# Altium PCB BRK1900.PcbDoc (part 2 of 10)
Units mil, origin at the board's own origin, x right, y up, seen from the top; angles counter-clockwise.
Board outline 8858.27 x 5905.51 mil, 10 copper layers (L1-TOP, L2-GND, L3-SIG1, L4-GND, L5-PWR, L6-PWR, L7-GND, L8-SIG2, L9-GND, L10-BOT), stack 48.824 mil thick; 507 components, 607 nets, 2498 pads, 2210 vias.
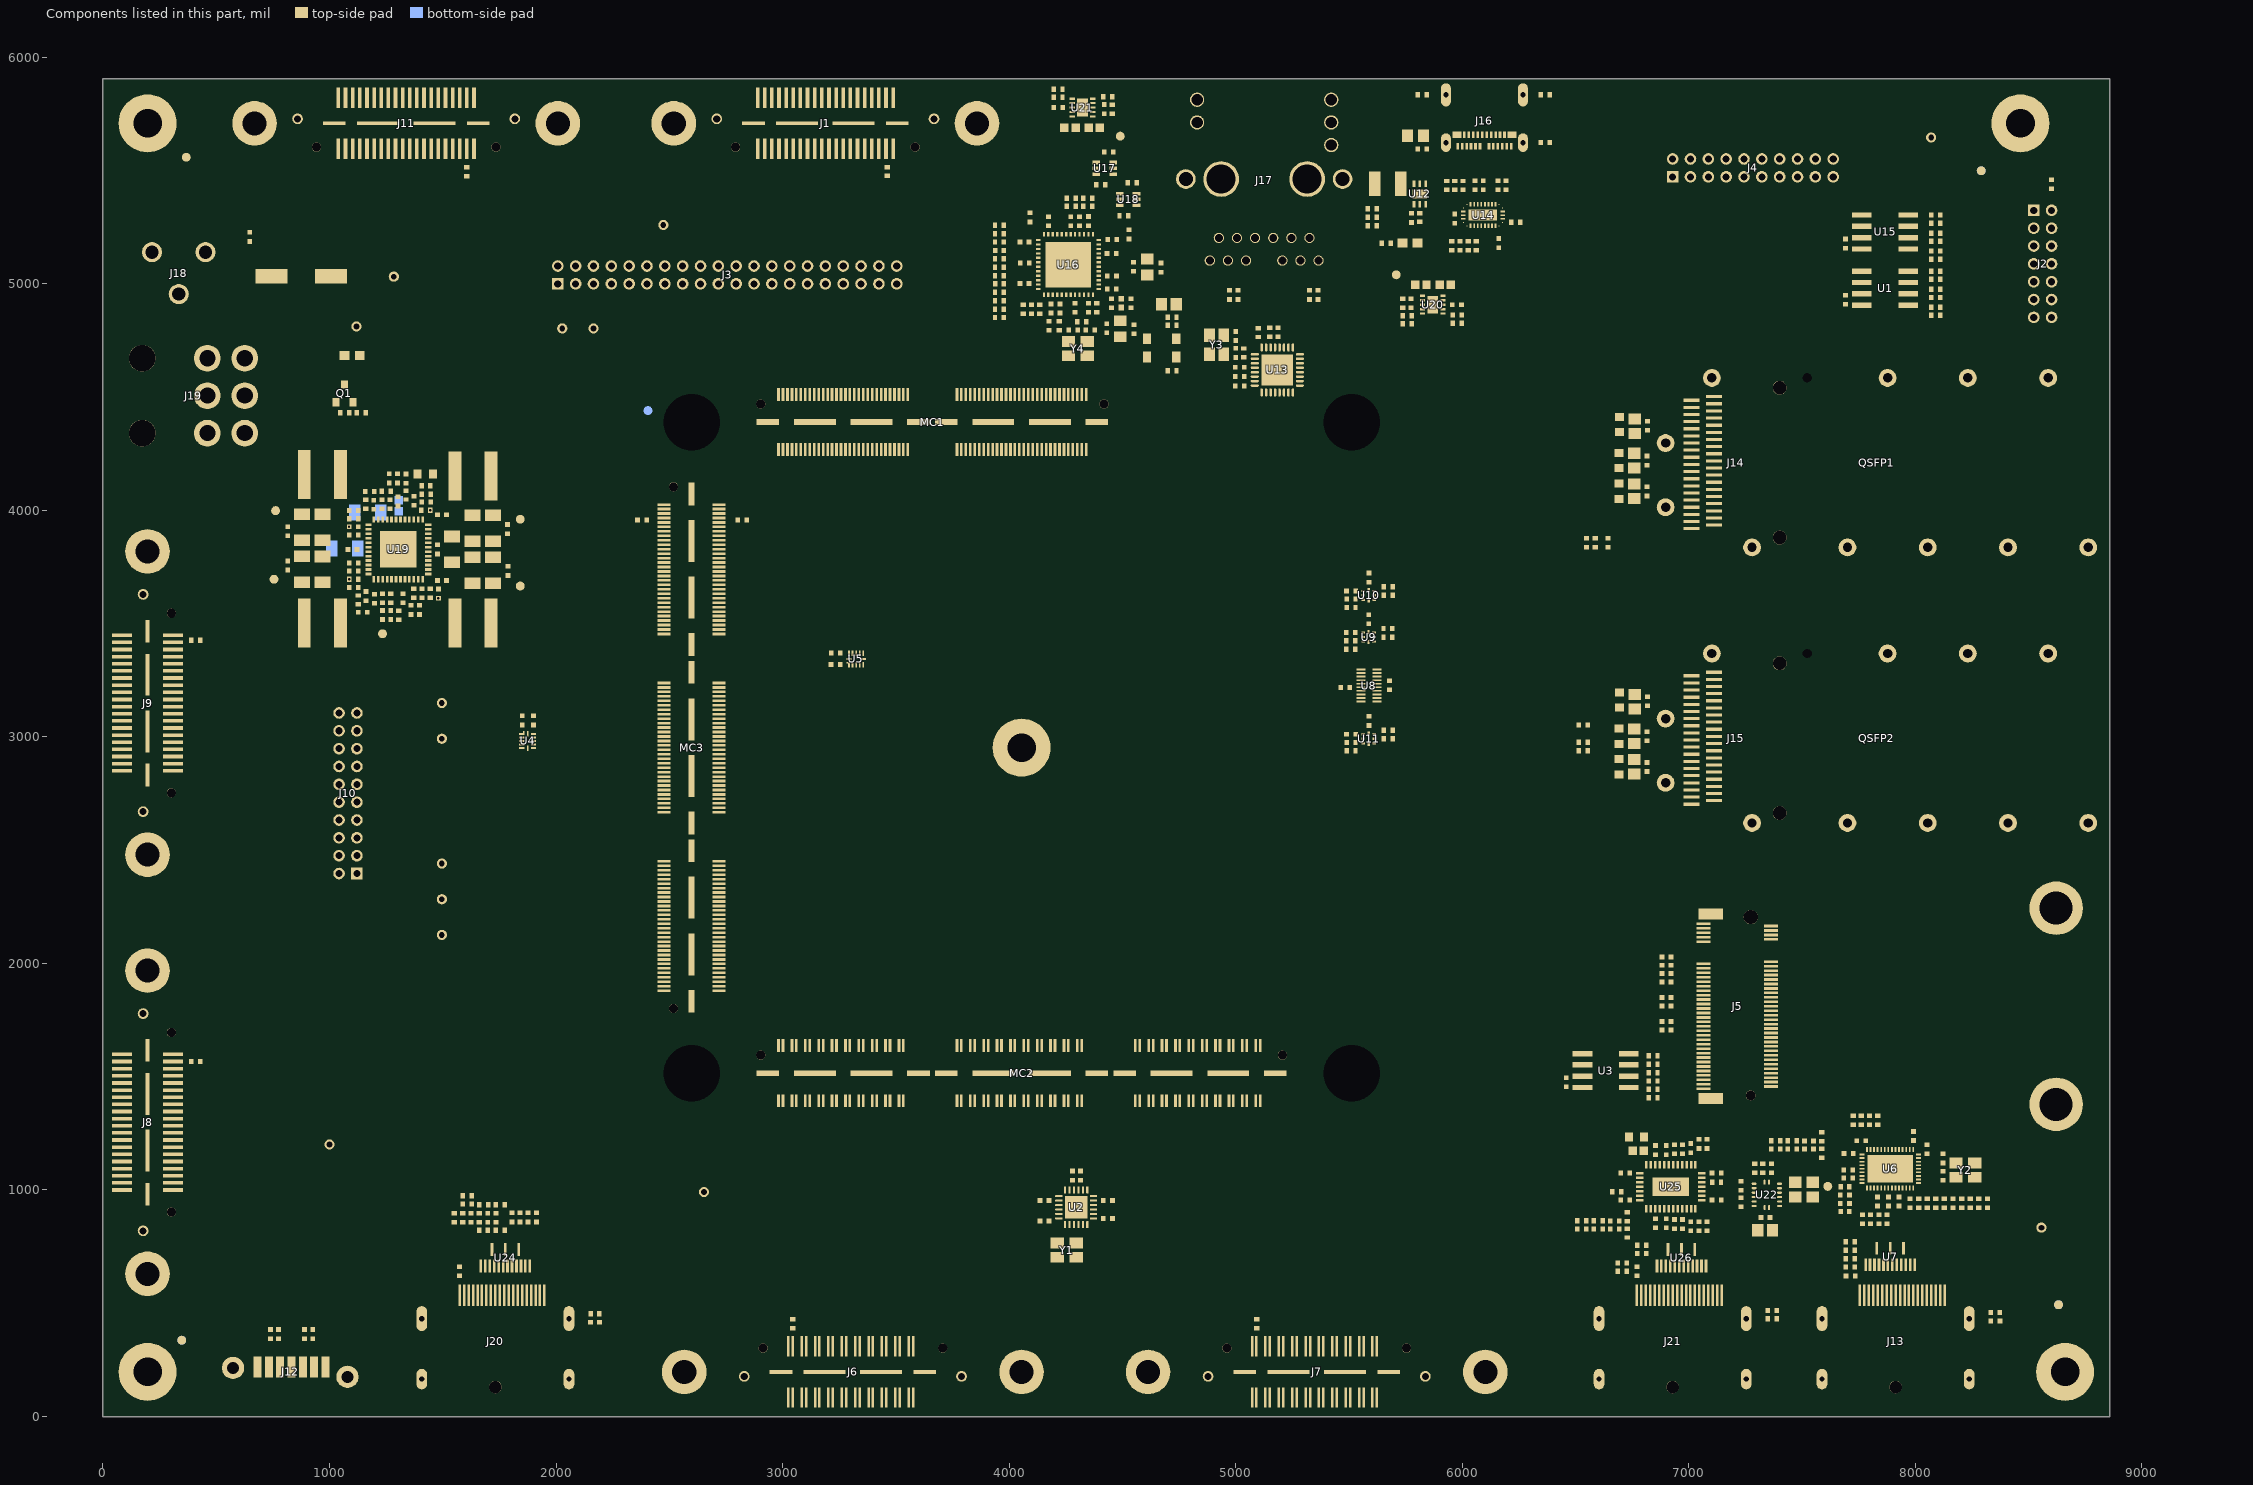
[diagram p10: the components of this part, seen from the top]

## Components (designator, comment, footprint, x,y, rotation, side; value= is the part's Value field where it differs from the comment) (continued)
R49 "CRCW04024K70JNED" RESC1005X06A#1 5673.46,3624.65 r0 top value="4.7 k"
R50 "SM-0402, 1%, 1/16W" RESC1005X06A#1 5508.46,3424.65 r180 top value="3.01 k"
R51 "SM-0402, 1%, 1/16W" RESC1005X06A#1 5508.46,3387.65 r180 top value="3.01 k"
R52 "CRCW06030000Z0EA" RESC1608N 6691.79,3003.24 r270 top value=0
R53 "CRCW06030000Z0EA" RESC1608N 6694,3163.18 r270 top value=0
R54 "CRCW06030000Z0EA" RESC1608N 6691.79,2868.24 r270 top value=0
R55 "SM-0402, 1%, 1/16W" RESC1005X06A#1 5509.46,3608.65 r180 top value="3.01 k"
R56 "SM-0402, 1%, 1/16W" RESC1005X06A#1 5509.46,3571.65 r180 top value="3.01 k"
R57 "CRCW04024K70JNED" RESC1005X06A#1 6535,3052.7 r180 top value="4.7 k"
R58 "CRCW04024K70JNED" RESC1005X06A#1 5672.46,3478.65 r0 top value="4.7 k"
R59 "CRCW04020000Z0ED" RESC1005X06A#1 6535,2976.7 r0 top value=0
R60 "CRCW04020000Z0ED" RESC1005X06A#1 6535,2938.7 r0 top value=0
R61 "SM-0402, 1%, 1/16W" RESC1005X06A#1 5509.46,2975.65 r180 top value="3.01 k"
R62 "SM-0402, 1%, 1/16W" RESC1005X06A#1 5509.46,2938.65 r180 top value="3.01 k"
R63 "CRCW04024K70JNED" RESC1005X06A#1 5673.46,3029.65 r0 top value="4.7 k"
R64 "CRCW04024K70JNED" RESC1005X06A#1 5673.46,2991.65 r0 top value="4.7 k"
R65 "CRCW04022K00FKED" RESC1005X06A#1 5665,5180 r180 top value="2.0 k"
R66 "CRCW040215K0FKED" RESC1005X06A#1 5813.06,5292.96 r90 top value="15 k"
R67 "CRCW04020000Z0ED" RESC1005X06A#2 5603,5331 r0 top value=0
R68 "CRCW040210K0FKED" RESC1005X06A#2 5603,5294 r0 top value="10.0 k"
R69 "CRCW04021K00FKED" RESC1005X06A#1 5150.41,4785.87 r270 top value="1 k"
R70 "CRCW04020000Z0ED" RESC1005X06A#2 5603,5257 r0 top value=0
R71 "CRCW0402499KFKEDC" RESC1005X06A#1 5990.41,5168.32 r270 top value="499 k"
R72 "CRCW0402887KFKED" RESC1005X06A#1 6062.41,5168.32 r270 top value="887 k"
R73 "CRCW04020000Z0ED" RESC1005X06A#1 5954.41,5168.32 r270 top value=0
R74 "CRCW040210K0FKED" RESC1005X06A#1 6026.41,5168.32 r270 top value="10.0 k"
R75 "CRCW04021M00JNED" RESC1005X06A#1 5036.41,4694.87 r270 top value="1 M"
R76 "CRCW04028K06FKED" RESC1005X06A#1 5100,4785 r270 top value="8.06 k"
R77 "CRCW04020000Z0ED" RESC1005X06A#1 6367,5834 r0 top value=0
R78 "CRCW04020000Z0ED" RESC1005X06A#1 5824,5834 r180 top value=0
R79 "CRCW04020000Z0ED" RESC1005X06A#1 6367,5624 r0 top value=0
R80 "CRCW040210K0FKED" RESC1005X06A#1 5931.41,5434.32 r90 top value="10.0 k"
R81 "CRCW040210K0FKED" RESC1005X06A#1 5967.41,5434.32 r90 top value="10.0 k"
R82 "CRCW0402210KFKED" RESC1005X06A#1 6236.09,5272.32 r0 top value="210 k"
R83 "CRCW040210K0FKED" RESC1005X06A#1 6003.41,5434.32 r270 top value="10.0 k"
R84 "CRCW040210K0FKED" RESC1005X06A#1 8091,5145 r0 top value="10.0 k"
R85 "CRCW040210K0FKED" RESC1005X06A#1 8091,5224 r0 top value="10.0 k"
R86 "CRCW040210K0FKED" RESC1005X06A#1 8091,5304 r0 top value="10.0 k"
R87 "CRCW040210K0FKED" RESC1005X06A#1 8091,5109 r180 top value="10.0 k"
R88 "CRCW040210K0FKED" RESC1005X06A#1 8091,5188 r180 top value="10.0 k"
R89 "CRCW040210K0FKED" RESC1005X06A#1 8091,5268 r180 top value="10.0 k"
R90 "CRCW04024K75FKED" RESC1005X06A#2 3957.49,4962.42 r180 top value="4.75 k"
R91 "CRCW04024K75FKED" RESC1005X06A#2 3957.49,4888.42 r180 top value="4.75 k"
R92 "CRCW04024K75FKED" RESC1005X06A#2 3957.49,5258.42 r180 top value="4.75 k"
R93 "CRCW04024K75FKED" RESC1005X06A#2 3957.49,5184.42 r180 top value="4.75 k"
R94 "CRCW04024K75FKED" RESC1005X06A#2 3957.49,5110.42 r180 top value="4.75 k"
R95 "CRCW04024K75FKED" RESC1005X06A#2 3957.49,5036.42 r180 top value="4.75 k"
R96 "CRCW0402240RFKED" RESC1005X06A#2 4405,5438 r180 top value=240
R97 "CRCW0402240RFKED" RESC1005X06A#2 4507,5300 r180 top value=240
R98 "CRCW04024K75FKED" RESC1005X06A#2 3957.49,4925.42 r0 top value="4.75 k"
R99 "CRCW04024K75FKED" RESC1005X06A#2 3957.49,4851.42 r0 top value="4.75 k"
R100 "CRCW04024K75FKED" RESC1005X06A#2 3957.49,5221.42 r0 top value="4.75 k"
R101 "CRCW04024K75FKED" RESC1005X06A#2 3957.57,5147.41 r0 top value="4.75 k"
R102 "CRCW04024K75FKED" RESC1005X06A#2 3957.39,5073.41 r0 top value="4.75 k"
R103 "CRCW04024K75FKED" RESC1005X06A#2 3957.63,4999.68 r0 top value="4.75 k"
R104 "CRCW040210K0FKED" RESC1005X06A#1 4440,5582 r180 top value="10.0 k"
R105 "CRCW04022K49FKED" RESC1005X06A#1 4062,4888 r270 top value="2.49 k"
R106 "CRCW04022K49FKED" RESC1005X06A#1 4099,4888 r270 top value="2.49 k"
R107 "CRCW04022K49FKED" RESC1005X06A#1 4136,4888 r270 top value="2.49 k"
R108 "CRCW04024K75FKED" RESC1005X06A#2 4176,4815 r270 top value="4.75 k"
R109 "CRCW040212K1FKED" RESC1005X06A#2 4387.06,4894.45 r270 top value="12.1 k"
R110 "CRCW040210K0FKED" RESC1005X06A#2 4275.06,5342.14 r180 top value="10.0 k"
R111 "CRCW040210K0FKED" RESC1005X06A#2 4346.74,5342.14 r0 top value="10.0 k"
R112 "CRCW040210K0FKED" RESC1005X06A#1 4543,5447 r180 top value="10.0 k"
R113 "CRCW04021M00JNED" RESC1005X06A#2 4321.06,4833.14 r180 top value="1 M"
R114 "CRCW04024K75FKED" RESC1005X06A#2 4222.06,4815.14 r90 top value="4.75 k"
R115 "CRCW04021K00FKED" RESC1005X06A#2 4275.06,5378.14 r0 top value="1 k"
R116 "CRCW04021K00FKED" RESC1005X06A#2 4346.74,5378.14 r180 top value="1 k"
R117 "CRCW04020000Z0ED" RESC1005X06A#2 4719.28,4616.57 r0 top value=0
R118 "CRCW04022K49FKED" RESC1005X06A#2 4719.28,4816.57 r180 top value="2.49 k"
R119 "CRCW040210K0FKED" RESC1005X06A#2 4719.28,4852.57 r0 top value="10.0 k"
R120 "CRCW040210K0FKED" RESC1005X06A#1 1270.29,3611.53 r270 top value="10.0 k"
R121 "CRCW040210K0FKED" RESC1005X06A#1 1250.29,4084.53 r0 top value="10.0 k"
R122 "SM-0402, 1%, 1/16W" RESC1005X06A#1 1444.58,3633.64 r270 top value="31.6 k"
R123 "SM-0402, 1%, 1/16W" RESC1005X06A#1 1408.58,3633.64 r90 top value="10.0 k"
R124 "CRCW040215K0FKED" RESC1005X06A#1 1372.58,3633.64 r270 top value="15 k"
R125 "SM-0402, 1%, 1/16W" RESC1005X06A#1 1425.27,4000.64 r0 top value="31.6 k"
R126 "SM-0402, 1%, 1/16W" RESC1005X06A#1 1426.58,4071.64 r180 top value="10.0 k"
R127 "CRCW040215K0FKED" RESC1005X06A#1 1337.58,4067.72 r90 top value="15 k"
R128 "CRCW040252K3FKED" RESC1005X06A#1 1106.58,3963.64 r180 top value="52.3 k"
R129 "CRCW040215K0FKED" RESC1005X06A#1 1159.58,4026.64 r90 top value="15 k"
R130 "SM-0402, 1%, 1/16W" RESC1005X06A#1 1106.58,3999.64 r0 top value="10.0 k"
R131 "CRCW040210K0FKED" RESC1005X06A#1 1234.29,3611.53 r270 top value="10.0 k"
R132 "CRCW040252K3FKED" RESC1005X06A#1 1106.58,3695.64 r180 top value="52.3 k"
R133 "CRCW040215K0FKED" RESC1005X06A#1 1126.29,3604.53 r270 top value="15 k"
R134 "CRCW0402374KFKED" RESC1005X06A#1 1305.4,3537.55 r90 top value="374 k"
R135 "SM-0402, 1%, 1/16W" RESC1005X06A#1 1106.9,3659.64 r0 top value="10.0 k"
R136 "CRCW06030000Z0EA" RESC1608N 1423,4160 r180 top value=0
R137 "CRCW040210K0JNED" RESC1005X06A#1 1426,4108 r0 top value="10 k"
R138 "CRCW04022K00FKED" RESC1005X06A#1 1140,4431 r180 top value="2.0 k"
R139 "CRCW040210K0FKED" RESC1005X06A#1 5737.94,4914.77 r90 top value="10.0 k"
R140 "CRCW040210K0FKED" RESC1005X06A#1 4456,5771.46 r270 top value="10.0 k"
R141 "CRCW0402237KFKED" RESC1005X06A#1 7327,1096.48 r90 top value="237 k"
R142 "CRCW04028K06FKED" RESC1005X06A#1 5757.94,4859.77 r180 top value="8.06 k"
R143 "CRCW040220K0FKED" RESC1005X06A#1 4436,5826.46 r0 top value="20.0 k"
R144 "CRCW040210R0FKED" RESC1005X06A#1 7231,945.48 r270 top value=10
R145 "CRCW04020000Z0ED" RESC1005X06A#1 5977.94,4862.77 r180 top value=0
R146 "CRCW04020000Z0ED" RESC1005X06A#1 4216,5823.46 r0 top value=0
R147 "CRCW0402237KFKED" RESC1005X06A#1 7291,1096.48 r270 top value="237 k"
R148 "CRCW040210K0FKED" RESC1005X06A#1 1068,4431 r0 top value="10.0 k"
R149 "CRCW040210K0JNED" RESC1005X06A#1 5758.25,4823.77 r180 top value="10 k"
R150 "CRCW04020000Z0ED" RESC1005X06A#1 5977.94,4826.77 r0 top value=0
R151 "CRCW04020000Z0ED" RESC1005X06A#1 4216,5859.46 r180 top value=0
R153 "CRCW040249R9FKEDC" RESC1005X06A#1 1753.53,935 r180 top value=49.9
R154 "CRCW0402100KFKED" RESC1005X06A#1 1754.21,822 r180 top value="100 k"
R155 "CRCW04021M00FKEDC" RESC1005X06A#1 2172,453 r180 top value="1 M"
R156 "CRCW04021M00FKEDC" RESC1005X06A#1 1550.53,878 r270 top value="1 M"
R157 "CRCW04021M00FKEDC" RESC1005X06A#1 1587.53,878 r270 top value="1 M"
R158 "CRCW040249R9FKEDC" RESC1005X06A#1 1680.53,935 r180 top value=49.9
R159 "CRCW0402100KFKED" RESC1005X06A#2 1624.53,878 r90 top value="100 k"
R160 "CRCW06030000Z0EA" RESC1608N 6769.36,1233.44 r0 top value=0
R161 "CRCW04021K20FKEDC" RESC1005X06A#1 6681.88,991.59 r0 top value="1.2 k"
R162 "CRCW04021M00FKEDC" RESC1005X06A#1 7369,431 r180 top value="1 M"
R163 "CRCW04021M00FKEDC" RESC1005X06A#1 6706.53,642 r0 top value="1 M"
R164 "CRCW04021M00FKEDC" RESC1005X06A#1 6706.53,678 r0 top value="1 M"
R165 "CRCW04020000Z0ED" RESC1005X06A#1 7122.83,1034.44 r180 top value=0
R166 "CRCW0402100KFKED" RESC1005X06A#1 6793.53,756 r180 top value="100 k"
R167 "CRCW0402100KFKED" RESC1005X06A#1 1679.84,822 r180 top value="100 k"
R168 "CRCW04022K49FKED" RESC1005X06A#1 1608.53,938 r180 top value="2.49 k"
R169 "CRCW04021K50FKED" RESC1005X06A#1 1608.53,975 r0 top value="1.5 k"
R170 "CRCW040249R9FKEDC" RESC1005X06A#1 6600,864 r0 top value=49.9
R171 "CRCW0402100KFKED" RESC1005X06A#1 6729,881.68 r270 top value="100 k"
R172 "CRCW040249R9FKEDC" RESC1005X06A#1 6600,828 r180 top value=49.9
R173 "CRCW0402100KFKED" RESC1005X06A#1 6729,810 r270 top value="100 k"
R174 "CRCW04022K49FKED" RESC1005X06A#1 6528,828 r180 top value="2.49 k"
R175 "CRCW04021K50FKED" RESC1005X06A#1 6528,864 r0 top value="1.5 k"
R176 "CRCW04022K49FKED" RESC1005X06A#1 7385,1217 r180 top value="2.49 k"
R177 "CRCW04021K50FKED" RESC1005X06A#1 7385,1181 r0 top value="1.5 k"
R178 "CRCW040249R9FKEDC" RESC1005X06A#1 7457,1217 r0 top value=49.9
R179 "CRCW040249R9FKEDC" RESC1005X06A#1 7457,1181 r180 top value=49.9
R180 "CRCW040210R0FKED" RESC1005X06A#1 7713.53,734 r0 top value=10
R181 "CRCW040210R0FKED" RESC1005X06A#1 1661.53,878 r270 top value=10
R182 "CRCW040210R0FKED" RESC1005X06A#1 6793.53,720 r0 top value=10
SO1 "Standoff" 9774025151R 8622.05,2244.09 r0 top locked
SO2 "Standoff" 9774025151R 8622.05,1377.95 r0 top locked
TP1 "+1.8V" TP-PTH-25/45 2653,991 r90 top
TP2 "DGND" TP-PTH-25/45 8557,834 r0 top
TP3 "+3.3V" TP-PTH-25/45 2165.35,4803.15 r90 top
TP4 "VREF_67" TP-PTH-25/45 1496.06,2992.13 r90 top
TP5 "DGND" TP-PTH-25/45 1000,1201 r90 top
TP6 "VCCO_28" TP-PTH-25/45 2474,5260 r90 top
TP7 "VCCO_68" TP-PTH-25/45 1496.06,2440.94 r90 top
TP8 "DGND" TP-PTH-25/45 1284,5032 r180 top
TP9 "VREF_28" TP-PTH-25/45 2027.56,4803.15 r90 top
TP10 "VREF_68" TP-PTH-25/45 1496.06,2283.46 r90 top
TP11 "DGND" TP-PTH-25/45 8070,5646 r90 top
TP12 "VCCO_67" TP-PTH-25/45 1119,4812 r90 top
TP13 "VCCO_87_88" TP-PTH-25/45 1496.06,2125.98 r90 top
TP14 "VCC_PSBATT" TP-PTH-25/45 1496.06,3149.61 r90 top
TP15 "+3.3V_QSFP" TP-SMD40 1842,3666 r90 top
TP16 "+3.3V_AUX" TP-SMD40 1842,3961 r90 top
TP17 "+5V_AUX" TP-SMD40 762,3999 r90 top
TP18 "+5V_SZG" TP-SMD40 755,3696 r90 top
TP19 "TESTPOINT-SMD40" TP-SMD40 1234.29,3455.53 r0 top
TP20 "+1.2V_DP" TP-SMD40 7614,1016 r90 top
TP21 "+1.8V_AUX" TP-SMD40 5709,5040 r90 top
TP22 "+1.2V_ETH" TP-SMD40 4491,5652 r90 top
U1 "24FC256-I/SN" SO-G8 7867,4981 r90 top
U2 "SI5338B-B-GM" Si5338 4296.23,923.79 r90 top
U3 "24FC256-I/SN" SO-G8 6633.6,1527.15 r90 top
U4 "TXB0304RUTR" PUQFN-N12 1875,2982 r0 top
U5 "TXB0304RUTR" PUQFN-N12 3325,3344 r90 top
U6 "MCDP6000C1" MCDP6000 7889.13,1093.63 r90 top
U7 "TPD8S009DSMR" TPD8S009DSMR 7889.17,706.42 r0 top locked
U8 "TXB0108DQSR" TXB0108DQSR 5588,3227 r270 top
U9 "FXMAR2102L8X" FXMAR2102L8X 5587,3441 r0 top
U10 "FXMAR2102L8X" FXMAR2102L8X 5588,3625 r0 top
U11 "FXMAR2102L8X" FXMAR2102L8X 5588,2992 r0 top
U12 "TPS2553DRV" S-PWSON-N6 5813,5397 r0 top
U13 "USB3320C-EZK" QFN-32 5183.95,4620.06 r90 top
U14 "HD3SS3220RNH" WQFN-30 6092.38,5303.24 r90 top
U15 "24AA025E48-I/SN" SO-G8 7867,5229 r90 top
U16 "KSZ9031RNXCA" QFN-48 4261.9,5085.28 r180 top
U17 "FDG6301" SOT363-6N 4422.23,5510 r0 top
U18 "FDG6301" SOT363-6N 4525,5373 r0 top
U19 "TPS65400RGZ" PVQFN-48 1303.58,3827.64 r180 top locked
U20 "TPS7A9001DSK" TPS7A90 5870,4908 r0 top
U21 "TPS7A9001DSK" TPS7A90 4323.94,5778.23 r180 top
U22 "EP53F8QI" EP53F8QI 7345,978.48 r180 top
U24 "TPD8S009DSMR" TPD8S009DSMR 1776.25,701.42 r0 top locked
U25 "SN65DP141RLJ" SN65DP141 6921.61,1014.88 r270 top
U26 "TPD8S009DSMR" TPD8S009DSMR 6967.98,701.27 r0 top locked
Y1 "FA-238 25.0000MB-C3" OSC_SMD_32x25 4254.23,734.79 r180 top
Y2 "ABM8-25.000MHZ-D2Y-T" OSC_SMD_32x25 8221.77,1087.26 r180 top
Y3 "T12BC1-19.200MHZ-T" OSC_SMD_32x25 4915.91,4730.6 r90 top
Y4 "ABM8-25.000MHZ-D2Y-T" OSC_SMD_32x25 4303.79,4713.64 r0 top

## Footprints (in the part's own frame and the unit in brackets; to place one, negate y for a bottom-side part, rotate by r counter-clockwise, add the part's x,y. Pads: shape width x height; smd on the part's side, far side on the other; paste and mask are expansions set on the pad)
0455580003 [mm]
  round 3 hole 3 unplated: 0(-4.2,7.3) 0(4.2,7.3)
  round 3 hole 1.8: 1(-4.2,0) 2(0,0) 3(4.2,0) 4(-4.2,-4.2) 5(0,-4.2) 6(4.2,-4.2)
  silkscreen extent -7,1 7,14
0472720001 [mm]
  rect 0.28x2.4 smd: 1(5.5,10.28) 2(5,10.28) 3(4.5,10.28) 4(4,10.28) 5(3.5,10.28) 6(3,10.28) 7(2.5,10.28) 8(2,10.28) 9(1.5,10.28) 10(1,10.28) 11(0.5,10.28) 12(0,10.28) 13(-0.5,10.28) 14(-1,10.28) 15(-1.5,10.28) 16(-2,10.28) 17(-2.5,10.28) 18(-3,10.28) 19(-3.5,10.28) 20(-4,10.28)
  round 1.4 hole 1.4 unplated paste-20 mask+0.076: M1(0,0)
  oval 1.2x2.8 hole 0.6 slot 2.2 at 90 deg paste-20 mask+0.076: SHELL1(-8.25,7.68) SHELL2(8.25,7.68)
  oval 1.2x2.3 hole 0.6 slot 1.7 at 90 deg paste-20 mask+0.076: SHELL3(8.25,0.9) SHELL4(-8.25,0.9)
  silkscreen extent -8.51,-4.4 8.5,10.2
1054500101 [mm]
  rect 0.3x0.7 smd: A1(1.32,0.41) A2(1.82,0.41) A3(2.32,0.41) A4(2.82,0.41) A5(3.32,0.41) A6(3.82,0.41) A7(4.82,0.41) A8(5.32,0.41) A9(5.82,0.41) A10(6.32,0.41) A11(6.82,0.41) A12(7.32,0.41) B2(6.57,-0.89) B3(6.07,-0.89) B4(5.57,-0.89) B5(5.07,-0.89) B6(4.57,-0.89) B7(4.07,-0.89) B8(3.57,-0.89) B9(3.07,-0.89) B10(2.57,-0.89) B11(2.07,-0.89)
  rect 1x0.7 smd: B1(7.42,-0.89) B12(1.22,-0.89)
  oval 1.1x2.1 hole 0.6 slot 1.6 at 90 deg: M1(0,0) M2(8.64,0)
  oval 1.1x2.6 hole 0.6 slot 2.1 at 90 deg: M3(8.64,-5.36) M4(0,-5.36)
  silkscreen extent -0.18,-7.3 8.82,-1.4
9774025151R [mm]
  round 6 hole 3.7: 1(0,0)
CAPAE9083X70N [mm] "Aluminum Electrolytic Capacitor, Body 8.30x8.30x7.00mm, IPC Medium Density"
  rect 3.6x1.65 smd: 1(-3.325,0) 2(3.325,0)
  silkscreen extent -4.25,-4.25 4.25,4.25
CAPC1005X06A#1 [mm] "Chip Capacitor, 2-Leads, Body 1.00x0.50mm, OK custom footprint"
  rect 0.52x0.55 smd mask+0.051: 1(-0.51,0) 2(0.51,0)
CAPC1005X06A#2 [mm] "Chip Capacitor, 2-Leads, Body 1.00x0.50mm, OK custom footprint"
  rect 0.52x0.55 smd: 1(-0.51,0) 2(0.51,0)
CAPC1608X09N [mm] "Chip Capacitor, 2-Leads, Body 1.60x0.80mm, IPC Medium Density"
  rect 0.95x0.95 smd: 1(-0.625,0) 2(0.625,0)
  silkscreen extent -0.8,-0.68 0.8,0.68, body extent -0.85,-0.45 0.85,0.45, height 0.9
CAPC2012X14N [mm] "Chip Capacitor, 2-Leads, Body 2.00x1.25mm, IPC Medium Density"
  rect 1.25x1.4 smd: 1(-0.825,0) 2(0.825,0)
  silkscreen extent -0.6,-0.88 0.6,0.88, body extent -1.05,-0.67 1.05,0.67, height 1.4
CAPC3216N [mm] "Chip Capacitor, Body 3.2x1.6mm, IPC Medium Density"
  rect 1.3x1.8 smd: 1(-1.45,0) 2(1.45,0)
  silkscreen extent -1.2,-1.08 1.2,1.08, body extent -1.7,-0.9 1.7,0.9, height 1.35
CAPC3225N [mm] "Chip Capacitor, Body 3.2x2.5mm, IPC Medium Density"
  rect 1.3x2.7 smd: 1(-1.45,0) 2(1.45,0)
  silkscreen extent -1.2,-1.53 1.2,1.53, body extent -1.7,-1.35 1.7,1.35, height 1.35
CD1608-0603-PIN1-CATHODE [mm] "Chip Diode; Body 1.6 x 0.8 mm (LxW typ)"
  rect 1.1x1 smd: 1(-0.85,0) 2(0.85,0)
  silkscreen extent -1.58,-0.68 0.6,0.68
CUI-PJ102A [mm] "2.1mm/5.5mm DC power jack"
  round 2.25 hole 1.5: 1(0,13.7) 2(0,7.7) 3(4.7,10.7)
  silkscreen extent -4.5,0 4.5,14.5
EP53F8QI [mm] "1.5A Voltage Mode Synchronous Buck PWM  DC-DC Converter"
  oval 0.55x0.25 smd mask+0.076: 1(-1.425,1.25) 2(-1.425,0.75) 3(-1.425,0.25) 4(-1.425,-0.25) 5(-1.425,-0.75) 6(-1.425,-1.25) 9(1.425,-1.25) 10(1.425,-0.75) 11(1.425,-0.25) 12(1.425,0.25) 13(1.425,0.75) 14(1.425,1.25)
  oval 0.25x0.55 smd mask+0.076: 7(-0.25,-1.425) 8(0.25,-1.425) 15(0.25,1.425) 16(-0.25,1.425)
  silkscreen extent -1.93,-1.56 1.5,1.93
FID1MM/2MM-SS [mm] "Fiducial 1mm copper, 2mm soldermask, single-side"
  round 1 smd paste-0.5 mask+0.5: FID?(0,0)
FXMAR2102L8X [mm]
  rect 0.4x0.25 smd mask+0.051: 1(-0.605,0.5) 2(-0.605,0) 3(-0.605,-0.5) 5(0.605,-0.5) 6(0.605,0) 7(0.605,0.5)
  rect 0.25x0.45 smd mask+0.051: 4(0,-0.575) 8(0,0.575)
HDR2X7-2MM [mm] "2mm 2x7 header"
  rect 1.3x1.3 hole 0.8: 1(-6,-1)
  round 1.3 hole 0.8: 2(-6,1) 3(-4,-1) 4(-4,1) 5(-2,-1) 6(-2,1) 7(0,-1) 8(0,1) 9(2,-1) 10(2,1) 11(4,-1) 12(4,1) 13(6,-1) 14(6,1)
  silkscreen extent -7,-2 7,2
HDR2X10-2MM [mm] "2mm 2x10 header"
  rect 1.3x1.3 hole 0.8: 1(-9,-1)
  round 1.3 hole 0.8: 2(-9,1) 3(-7,-1) 4(-7,1) 5(-5,-1) 6(-5,1) 7(-3,-1) 8(-3,1) 9(-1,-1) 10(-1,1) 11(1,-1) 12(1,1) 13(3,-1) 14(3,1) 15(5,-1) 16(5,1) 17(7,-1) 18(7,1) 19(9,-1) 20(9,1)
  silkscreen extent -10,-2 10,2
HDR2X20-2MM [mm] "2mm 2x20 header"
  rect 1.3x1.3 hole 0.8: 1(-19,-1)
  round 1.3 hole 0.8: 2(-19,1) 3(-17,-1) 4(-17,1) 5(-15,-1) 6(-15,1) 7(-13,-1) 8(-13,1) 9(-11,-1) 10(-11,1) 11(-9,-1) 12(-9,1) 13(-7,-1) 14(-7,1) 15(-5,-1) 16(-5,1) 17(-3,-1) 18(-3,1) 19(-1,-1) 20(-1,1) 21(1,-1) 22(1,1) 23(3,-1) 24(3,1) 25(5,-1) 26(5,1) 27(7,-1) 28(7,1) 29(9,-1) 30(9,1) 31(11,-1) 32(11,1) 33(13,-1) 34(13,1) 35(15,-1) 36(15,1) 37(17,-1) 38(17,1) 39(19,-1) 40(19,1)
  silkscreen extent -20,-2 20,2
INDC1005X05N [mm] "Chip Inductor, 2-Leads, Body 1.01x0.50mm, IPC Medium Density"
  rect 0.66x0.64 smd: 1(-0.5,0) 2(0.5,0)
  body extent -0.61,-0.3 0.61,0.3, height 0.5
JSO-0515-01 [mil]
  round 0 hole 250 unplated: 1(0,0)
  Keep-Out Layer region: 0,-157.48 -60.27,-145.49 -111.36,-111.36 -145.49,-60.27 -157.48,0 -157.48,0 -145.49,60.27 -111.36,111.36 -60.27,145.49 0,157.48 0,157.48 60.27,145.49 111.36,111.36 145.49,60.27 157.48,0 157.48,0 145.49,-60.27 111.36,-111.36 60.27,-145.49 0,-157.48
L829-1J1T-43 [mm] "Ethernet MagJack"
  round 1.15 hole 0.89: 1(5.08,6.604) 2(3.048,6.604) 3(1.016,6.604) 4(-1.016,6.604) 5(-3.048,6.604) 6(-5.08,6.604) 7(6.096,9.144) 8(4.064,9.144) 9(2.032,9.144) 10(-2.032,9.144) 11(-4.064,9.144) 12(-6.096,9.144)
  round 1.6 hole 1.27: 13(7.52,-6.35) 14(7.52,-8.89) 15(-7.52,-3.81) 16(-7.52,-6.35) 17(-7.52,-8.89)
  round 2.2 hole 1.575: S1(-8.79,0) S2(8.79,0)
  round 4 hole 3.251: T1(-4.825,0) T2(4.825,0)
  silkscreen extent -8.9,-13.3 8.9,10.9
M2-CONNECTOR_M-KEYING [mm] "M-2 Connector, 67-pin, M Keying"
  rect 1.2x2.75 smd mask+0.051: 1(-10.35,4.5) 1(10.35,4.5)
  rect 0.3x1.55 smd mask+0.051: 1(-9.25,5.275) 2(-9,-2.275) 3(-8.75,5.275) 4(-8.5,-2.275) 5(-8.25,5.275) 6(-8,-2.275) 7(-7.75,5.275) 8(-7.5,-2.275) 9(-7.25,5.275) 10(-7,-2.275) 11(-6.75,5.275) 12(-6.5,-2.275) 13(-6.25,5.275) 14(-6,-2.275) 15(-5.75,5.275) 16(-5.5,-2.275) 17(-5.25,5.275) 18(-5,-2.275) 19(-4.75,5.275) 20(-4.5,-2.275) 21(-4.25,5.275) 22(-4,-2.275) 23(-3.75,5.275) 24(-3.5,-2.275) 25(-3.25,5.275) 26(-3,-2.275) 27(-2.75,5.275) 28(-2.5,-2.275) 29(-2.25,5.275) 30(-2,-2.275) 31(-1.75,5.275) 32(-1.5,-2.275) 33(-1.25,5.275) 34(-1,-2.275) 35(-0.75,5.275) 36(-0.5,-2.275) 37(-0.25,5.275) 38(0,-2.275) 39(0.25,5.275) 40(0.5,-2.275) 41(0.75,5.275) 42(1,-2.275) 43(1.25,5.275) 44(1.5,-2.275) 45(1.75,5.275) 46(2,-2.275) 47(2.25,5.275) 48(2.5,-2.275) 49(2.75,5.275) 50(3,-2.275) 51(3.25,5.275) 52(3.5,-2.275) 53(3.75,5.275) 54(4,-2.275) 55(4.25,5.275) 56(4.5,-2.275) 57(4.75,5.275) 58(5,-2.275) 67(7.25,5.275) 68(7.5,-2.275) 69(7.75,5.275) 70(8,-2.275) 71(8.25,5.275) 72(8.5,-2.275) 73(8.75,5.275) 74(9,-2.275) 75(9.25,5.275)
  round 1.1 hole 1.1 unplated paste+0: MH(-10,0)
  round 1.6 hole 1.6 unplated paste+0: MH(10,0)
  silkscreen extent -11,-2.55 11,5.3
MCDP6000 [mm]
  rect 0.2x0.55 smd: 1(-1.6,-3.175) 2(-1.2,-3.175) 3(-0.8,-3.175) 4(-0.4,-3.175) 5(0,-3.175) 6(0.4,-3.175) 7(0.8,-3.175) 8(1.2,-3.175) 9(1.6,-3.175) 24(1.6,3.175) 25(1.2,3.175) 26(0.8,3.175) 27(0.4,3.175) 28(0,3.175) 29(-0.4,3.175) 30(-0.8,3.175) 31(-1.2,3.175) 32(-1.6,3.175)
  rect 0.55x0.2 smd: 10(2.175,-2.6) 11(2.175,-2.2) 12(2.175,-1.8) 13(2.175,-1.4) 14(2.175,-1) 15(2.175,-0.6) 16(2.175,-0.2) 17(2.175,0.2) 18(2.175,0.6) 19(2.175,1) 20(2.175,1.4) 21(2.175,1.8) 22(2.175,2.2) 23(2.175,2.6) 33(-2.175,2.6) 34(-2.175,2.2) 35(-2.175,1.8) 36(-2.175,1.4) 37(-2.175,1) 38(-2.175,0.6) 39(-2.175,0.2) 40(-2.175,-0.2) 41(-2.175,-0.6) 42(-2.175,-1) 43(-2.175,-1.4) 44(-2.175,-1.8) 45(-2.175,-2.2) 46(-2.175,-2.6)
  rect 3.1x5.1 smd paste-5: PAD(0,0)
  silkscreen extent -2.65,-3.65 2.29,3.3
MOLEX-67800-5005 [mm]
  rect 0.9x2.4 smd: 1(3.955,0.55) 2(2.685,0.55) 3(1.415,0.55) 4(0.145,0.55) 5(-1.125,0.55) 6(-2.395,0.55) 7(-3.665,0.55)
  round 2.5 hole 1.35: MH(-6.415,0.45) MH(6.415,-0.55)
  silkscreen extent -8.65,-3.9 8.6,2.85
MTG-2.7/5.0-PTH [mm] "Mounting hole, 2.7mm ID, 5.0mm OD, plated"
  round 5 / inner round 3.175 / far side round 5 hole 2.7: 1(0,0)
MTG-3.2/6.5-PTH [mm] "Mounting hole, 3.2mm ID, 6.5mm OD, plated"
  round 6.5 hole 3.2: 1(0,0)
okLogo-23x5 [mil] "Opal Kelly silkscreen logo (23mm x 5mm)"
  silkscreen extent -3,-82 266,82
OSC_SMD_32x25 [mm] "3.2x2.5mm SMD clock oscillator"
  rect 1.5x1.2 smd: 1(-1.06,-0.8) 2(1.06,-0.8) 3(1.06,0.8) 4(-1.06,0.8)
  silkscreen extent -1.98,-1.42 1.98,0.8
PUQFN-N12 [mm] "0.4A"
  rect 0.6x0.2 smd: 1(-0.65,0.8) 2(-0.65,0.4) 3(-0.65,0) 4(-0.65,-0.4) 5(-0.65,-0.8) 7(0.65,-0.8) 8(0.65,-0.4) 9(0.65,0) 10(0.65,0.4) 11(0.65,0.8)
  rect 0.15x0.4 smd: 1(-0.425,0.9)
  rect 0.2x0.6 smd mask+0.076: 6(0,-0.8) 12(0,0.8)
  silkscreen extent -1.13,-1.08 0.86,1.08, body extent -0.85,-1 0.85,1, height 0.5
PVQFN-48 [mm]
  rect 0.7x0.3 smd mask+0.051: 1(-3.35,2.75) 2(-3.35,2.25) 3(-3.35,1.75) 4(-3.35,1.25) 5(-3.35,0.75) 6(-3.35,0.25) 7(-3.35,-0.25) 8(-3.35,-0.75) 9(-3.35,-1.25) 10(-3.35,-1.75) 11(-3.35,-2.25) 12(-3.35,-2.75) 25(3.35,-2.75) 26(3.35,-2.25) 27(3.35,-1.75) 28(3.35,-1.25) 29(3.35,-0.75) 30(3.35,-0.25) 31(3.35,0.25) 32(3.35,0.75) 33(3.35,1.25) 34(3.35,1.75) 35(3.35,2.25) 36(3.35,2.75)
  rect 0.3x0.7 smd mask+0.051: 13(-2.75,-3.35) 14(-2.25,-3.35) 15(-1.75,-3.35) 16(-1.25,-3.35) 17(-0.75,-3.35) 18(-0.25,-3.35) 19(0.25,-3.35) 20(0.75,-3.35) 21(1.25,-3.35) 22(1.75,-3.35) 23(2.25,-3.35) 24(2.75,-3.35) 37(2.75,3.35) 38(2.25,3.35) 39(1.75,3.35) 40(1.25,3.35) 41(0.75,3.35) 42(0.25,3.35) 43(-0.25,3.35) 44(-0.75,3.35) 45(-1.25,3.35) 46(-1.75,3.35) 47(-2.25,3.35) 48(-2.75,3.35)
  rect 4.08x4.08 smd mask+0.051: PAD(0,0)
  silkscreen extent -3.89,-3.6 3.6,3.89
QFN-32 [mm] "5x5mm QFN-32 (Modified QFN50P500X500-32V6M)"
  rect 3.5x3.5 smd: 0(0,0)
  oval 0.91x0.28 smd: 1(-2.525,1.75) 2(-2.525,1.25) 3(-2.525,0.75) 4(-2.525,0.25) 5(-2.525,-0.25) 6(-2.525,-0.75) 7(-2.525,-1.25) 8(-2.525,-1.75) 17(2.525,-1.75) 18(2.525,-1.25) 19(2.525,-0.75) 20(2.525,-0.25) 21(2.525,0.25) 22(2.525,0.75) 23(2.525,1.25) 24(2.525,1.75)
  oval 0.28x0.91 smd: 9(-1.75,-2.525) 10(-1.25,-2.525) 11(-0.75,-2.525) 12(-0.25,-2.525) 13(0.25,-2.525) 14(0.75,-2.525) 15(1.25,-2.525) 16(1.75,-2.525) 25(1.75,2.525) 26(1.25,2.525) 27(0.75,2.525) 28(0.25,2.525) 29(-0.25,2.525) 30(-0.75,2.525) 31(-1.25,2.525) 32(-1.75,2.525)
  silkscreen extent -3.18,-2.52 2.52,3.18
QFN-48 [mm] "7x7mm QFN-48"
  rect 5.1x5.1 smd: 0(0,0)
  rect 0.5x0.25 smd: 1(-3.4,2.75) 2(-3.4,2.25) 3(-3.4,1.75) 4(-3.4,1.25) 5(-3.4,0.75) 6(-3.4,0.25) 7(-3.4,-0.25) 8(-3.4,-0.75) 9(-3.4,-1.25) 10(-3.4,-1.75) 11(-3.4,-2.25) 12(-3.4,-2.75) 25(3.4,-2.75) 26(3.4,-2.25) 27(3.4,-1.75) 28(3.4,-1.25) 29(3.4,-0.75) 30(3.4,-0.25) 31(3.4,0.25) 32(3.4,0.75) 33(3.4,1.25) 34(3.4,1.75) 35(3.4,2.25) 36(3.4,2.75)
  rect 0.25x0.5 smd: 13(-2.75,-3.4) 14(-2.25,-3.4) 15(-1.75,-3.4) 16(-1.25,-3.4) 17(-0.75,-3.4) 18(-0.25,-3.4) 19(0.25,-3.4) 20(0.75,-3.4) 21(1.25,-3.4) 22(1.75,-3.4) 23(2.25,-3.4) 24(2.75,-3.4) 37(2.75,3.4) 38(2.25,3.4) 39(1.75,3.4) 40(1.25,3.4) 41(0.75,3.4) 42(0.25,3.4) 43(-0.25,3.4) 44(-0.75,3.4) 45(-1.25,3.4) 46(-1.75,3.4) 47(-2.25,3.4) 48(-2.75,3.4)
  silkscreen extent -3.83,-3.5 3.5,3.83
QSE-020-01-X-D-A-L [mil] "0.80mm, 40 pin Surface Mount connectors with Ground Strip"
  rect 100x17 smd paste+0: 0(-317.45,0) 0(317.55,0)
  rect 185x17 smd paste+0: 0(-124.95,0) 0(125.05,0)
  rect 16x89.5 smd paste+0: 1(-299.25,-112.8) 2(-299.25,112.8) 3(-267.75,-112.8) 4(-267.75,112.8) 5(-236.25,-112.8) 6(-236.25,112.8) 7(-204.75,-112.8) 8(-204.75,112.8) 9(-173.25,-112.8) 10(-173.25,112.8) 11(-141.75,-112.8) 12(-141.75,112.8) 13(-110.25,-112.8) 14(-110.25,112.8) 15(-78.75,-112.8) 16(-78.75,112.8) 17(-47.25,-112.8) 18(-47.25,112.8) 19(-15.75,-112.8) 20(-15.75,112.8) 21(15.75,-112.8) 22(15.75,112.8) 23(47.25,-112.8) 24(47.25,112.8) 25(78.75,-112.8) 26(78.75,112.8) 27(110.25,-112.8) 28(110.25,112.8) 29(141.75,-112.8) 30(141.75,112.8) 31(173.25,-112.8) 32(173.25,112.8) 33(204.75,-112.8) 34(204.75,112.8) 35(236.25,-112.8) 36(236.25,112.8) 37(267.75,-112.8) 38(267.75,112.8) 39(299.25,-112.8) 40(299.25,112.8)
  round 47.24 hole 31.5 paste+0: MH(-479.48,-19.69) MH(479.58,-19.69)
  round 40.16 hole 40.16 unplated paste+0: MH(-396.25,105) MH(396.35,105)
  silkscreen extent -528,-146 528,146
QSFP28_RECEPTACLE_SFF-8679 [mm]
  rect 0.35x1.8 smd: 1(1.4,7.37) 2(2.2,7.37) 3(3,7.37) 4(3.8,7.37) 5(4.6,7.37) 6(5.4,7.37) 7(6.2,7.37) 8(7,7.37) 9(7.8,7.37) 10(8.6,7.37) 11(9.4,7.37) 12(10.2,7.37) 13(11,7.37) 14(11.8,7.37) 15(12.6,7.37) 16(13.4,7.37) 17(14.2,7.37) 18(15,7.37) 19(15.8,7.37) 20(15.4,9.88) 21(14.6,9.88) 22(13.8,9.88) 23(13,9.88) 24(12.2,9.88) 25(11.4,9.88) 26(10.6,9.88) 27(9.8,9.88) 28(9,9.88) 29(8.2,9.88) 30(7.4,9.88) 31(6.6,9.88) 32(5.8,9.88) 33(5,9.88) 34(4.2,9.88) 35(3.4,9.88) 36(2.6,9.88) 37(1.8,9.88) 38(1,9.88)
  round 1.55 hole 1.55 unplated: MH(0,0) MH(16.8,0)
  L1-TOP keep-out region: 16.3,-3.16 17.3,-3.16 17.3,-2.16 16.3,-2.16
  L1-TOP keep-out region: -0.5,-3.16 0.5,-3.16 0.5,-2.16 -0.5,-2.16
  silkscreen extent -0.8,-3 17.6,9.7
QSFP28_SINGLE_CAGE [mm]
  round 2 hole 1.05: 0(-1.1,3.1) 0(-1.1,-7.6) 0(-1.1,-16.6) 0(-1.1,-25.6) 0(-1.1,-34.6) 0(3.4,12.79) 0(10.6,12.79) 0(17.9,-21.1) 0(17.9,-12.1) 0(17.9,7.6) 0(17.9,-30.1)
  round 0 hole 1.05 unplated: 0(17.9,-3.1)
  L1-TOP keep-out region: -2.7,13.5 -2.7,-37 19.5,-37 19.5,13.5 16.5,13.5 16.5,11.1 18,11.1 18,-1.6 15.9,-1.6 15.9,-3.5 0.9,-3.5 0.9,-1.6 -1.2,-1.6 -1.2,11.1 0.3,11.1 0.3,13.5
  silkscreen extent -1.1,-48.2 17.9,12.9
QSH-020-01-X-D-DP-A-L [mm] "0.5mm hi-speed, high-density header (male), 80-pin, latching, ground protection in middle"
  rect 2.54x0.43 smd mask+0.051: 0(-8.07,0) 0(8.06,0)
  rect 4.7x0.43 smd mask+0.051: 0(-3.18,0) 0(3.17,0)
  rect 0.28x2.27 smd mask+0.051: 1(-7.25,-2.87) 2(-7.25,2.87) 3(-6.75,-2.87) 4(-6.75,2.87) 5(-5.75,-2.87) 6(-5.75,2.87) 7(-5.25,-2.87) 8(-5.25,2.87) 9(-4.25,-2.87) 10(-4.25,2.87) 11(-3.75,-2.87) 12(-3.75,2.87) 13(-2.75,-2.87) 14(-2.75,2.87) 15(-2.25,-2.87) 16(-2.25,2.87) 17(-1.25,-2.87) 18(-1.25,2.87) 19(-0.75,-2.87) 20(-0.75,2.87) 21(0.25,-2.87) 22(0.25,2.87) 23(0.75,-2.87) 24(0.75,2.87) 25(1.75,-2.87) 26(1.75,2.87) 27(2.25,-2.87) 28(2.25,2.87) 29(3.25,-2.87) 30(3.25,2.87) 31(3.75,-2.87) 32(3.75,2.87) 33(4.75,-2.87) 34(4.75,2.87) 35(5.25,-2.87) 36(5.25,2.87) 37(6.25,-2.87) 38(6.25,2.87) 39(6.75,-2.87) 40(6.75,2.87)
  round 1.2 hole 0.8 paste+0 mask+0.076: MH(-12.18,-0.5) MH(12.18,-0.5)
  round 1.02 hole 1.02 unplated paste+0: MH(-10.07,2.67) MH(10.07,2.67)
  silkscreen extent -13.4,-3.7 13.4,3.7
QTH-060-01-X-D [mm]
  rect 2.54x0.64 smd: 0(-18.445,0) 0(-1.555,0) 0(1.555,0) 0(18.445,0)
  rect 4.7x0.64 smd: 0(-13.175,0) 0(-6.825,0) 0(6.825,0) 0(13.175,0)
  rect 0.3x1.45 smd: 1(-17.25,3.09) 2(-17.25,-3.09) 3(-16.75,3.09) 4(-16.75,-3.09) 5(-16.25,3.09) 6(-16.25,-3.09) 7(-15.75,3.09) 8(-15.75,-3.09) 9(-15.25,3.09) 10(-15.25,-3.09) 11(-14.75,3.09) 12(-14.75,-3.09) 13(-14.25,3.09) 14(-14.25,-3.09) 15(-13.75,3.09) 16(-13.75,-3.09) 17(-13.25,3.09) 18(-13.25,-3.09) 19(-12.75,3.09) 20(-12.75,-3.09) 21(-12.25,3.09) 22(-12.25,-3.09) 23(-11.75,3.09) 24(-11.75,-3.09) 25(-11.25,3.09) 26(-11.25,-3.09) 27(-10.75,3.09) 28(-10.75,-3.09) 29(-10.25,3.09) 30(-10.25,-3.09) 31(-9.75,3.09) 32(-9.75,-3.09) 33(-9.25,3.09) 34(-9.25,-3.09) 35(-8.75,3.09) 36(-8.75,-3.09) 37(-8.25,3.09) 38(-8.25,-3.09) 39(-7.75,3.09) 40(-7.75,-3.09) 41(-7.25,3.09) 42(-7.25,-3.09) 43(-6.75,3.09) 44(-6.75,-3.09) 45(-6.25,3.09) 46(-6.25,-3.09) 47(-5.75,3.09) 48(-5.75,-3.09) 49(-5.25,3.09) 50(-5.25,-3.09) 51(-4.75,3.09) 52(-4.75,-3.09) 53(-4.25,3.09) 54(-4.25,-3.09) 55(-3.75,3.09) 56(-3.75,-3.09) 57(-3.25,3.09) 58(-3.25,-3.09) 59(-2.75,3.09) 60(-2.75,-3.09) 61(2.75,3.09) 62(2.75,-3.09) 63(3.25,3.09) 64(3.25,-3.09) 65(3.75,3.09) 66(3.75,-3.09) 67(4.25,3.09) 68(4.25,-3.09) 69(4.75,3.09) 70(4.75,-3.09) 71(5.25,3.09) 72(5.25,-3.09) 73(5.75,3.09) 74(5.75,-3.09) 75(6.25,3.09) 76(6.25,-3.09) 77(6.75,3.09) 78(6.75,-3.09) 79(7.25,3.09) 80(7.25,-3.09) 81(7.75,3.09) 82(7.75,-3.09) 83(8.25,3.09) 84(8.25,-3.09) 85(8.75,3.09) 86(8.75,-3.09) 87(9.25,3.09) 88(9.25,-3.09) 89(9.75,3.09) 90(9.75,-3.09) 91(10.25,3.09) 92(10.25,-3.09) 93(10.75,3.09) 94(10.75,-3.09) 95(11.25,3.09) 96(11.25,-3.09) 97(11.75,3.09) 98(11.75,-3.09) 99(12.25,3.09) 100(12.25,-3.09) 101(12.75,3.09) 102(12.75,-3.09) 103(13.25,3.09) 104(13.25,-3.09) 105(13.75,3.09) 106(13.75,-3.09) 107(14.25,3.09) 108(14.25,-3.09) 109(14.75,3.09) 110(14.75,-3.09) 111(15.25,3.09) 112(15.25,-3.09) 113(15.75,3.09) 114(15.75,-3.09) 115(16.25,3.09) 116(16.25,-3.09) 117(16.75,3.09) 118(16.75,-3.09) 119(17.25,3.09) 120(17.25,-3.09)
  round 1.02 hole 1.02 unplated: MH(-19.24,2.03) MH(19.24,2.03)
  silkscreen extent -20.05,-3.05 20.05,3.05
QTH-060-01-X-D-DP-A [mm]
  rect 2.54x0.64 smd: 0(-28.445,0) 0(-11.555,0) 0(-8.445,0) 0(8.445,0) 0(11.555,0) 0(28.445,0)
  rect 4.7x0.64 smd: 0(-23.175,0) 0(-16.825,0) 0(-3.175,0) 0(3.175,0) 0(16.825,0) 0(23.175,0)
  rect 0.3x1.45 smd: 1(-27.25,3.09) 2(-27.25,-3.09) 3(-26.75,3.09) 4(-26.75,-3.09) 5(-25.75,3.09) 6(-25.75,-3.09) 7(-25.25,3.09) 8(-25.25,-3.09) 9(-24.25,3.09) 10(-24.25,-3.09) 11(-23.75,3.09) 12(-23.75,-3.09) 13(-22.75,3.09) 14(-22.75,-3.09) 15(-22.25,3.09) 16(-22.25,-3.09) 17(-21.25,3.09) 18(-21.25,-3.09) 19(-20.75,3.09) 20(-20.75,-3.09) 21(-19.75,3.09) 22(-19.75,-3.09) 23(-19.25,3.09) 24(-19.25,-3.09) 25(-18.25,3.09) 26(-18.25,-3.09) 27(-17.75,3.09) 28(-17.75,-3.09) 29(-16.75,3.09) 30(-16.75,-3.09) 31(-16.25,3.09) 32(-16.25,-3.09) 33(-15.25,3.09) 34(-15.25,-3.09) 35(-14.75,3.09) 36(-14.75,-3.09) 37(-13.75,3.09) 38(-13.75,-3.09) 39(-13.25,3.09) 40(-13.25,-3.09) 41(-7.25,3.09) 42(-7.25,-3.09) 43(-6.75,3.09) 44(-6.75,-3.09) 45(-5.75,3.09) 46(-5.75,-3.09) 47(-5.25,3.09) 48(-5.25,-3.09) 49(-4.25,3.09) 50(-4.25,-3.09) 51(-3.75,3.09) 52(-3.75,-3.09) 53(-2.75,3.09) 54(-2.75,-3.09) 55(-2.25,3.09) 56(-2.25,-3.09) 57(-1.25,3.09) 58(-1.25,-3.09) 59(-0.75,3.09) 60(-0.75,-3.09) 61(0.25,3.09) 62(0.25,-3.09) 63(0.75,3.09) 64(0.75,-3.09) 65(1.75,3.09) 66(1.75,-3.09) 67(2.25,3.09) 68(2.25,-3.09) 69(3.25,3.09) 70(3.25,-3.09) 71(3.75,3.09) 72(3.75,-3.09) 73(4.75,3.09) 74(4.75,-3.09) 75(5.25,3.09) 76(5.25,-3.09) 77(6.25,3.09) 78(6.25,-3.09) 79(6.75,3.09) 80(6.75,-3.09) 81(12.75,3.09) 82(12.75,-3.09) 83(13.25,3.09) 84(13.25,-3.09) 85(14.25,3.09) 86(14.25,-3.09) 87(14.75,3.09) 88(14.75,-3.09) 89(15.75,3.09) 90(15.75,-3.09) 91(16.25,3.09) 92(16.25,-3.09) 93(17.25,3.09) 94(17.25,-3.09) 95(17.75,3.09) 96(17.75,-3.09) 97(18.75,3.09) 98(18.75,-3.09) 99(19.25,3.09) 100(19.25,-3.09) 101(20.25,3.09) 102(20.25,-3.09) 103(20.75,3.09) 104(20.75,-3.09) 105(21.75,3.09) 106(21.75,-3.09) 107(22.25,3.09) 108(22.25,-3.09) 109(23.25,3.09) 110(23.25,-3.09) 111(23.75,3.09) 112(23.75,-3.09) 113(24.75,3.09) 114(24.75,-3.09) 115(25.25,3.09) 116(25.25,-3.09) 117(26.25,3.09) 118(26.25,-3.09) 119(26.75,3.09) 120(26.75,-3.09)
  round 1.02 hole 1.02 unplated: MH(-29.24,2.03) MH(29.24,2.03)
  silkscreen extent -30.05,-3.05 30.05,3.05
QTH-090-01-X-D [mm]
  rect 2.54x0.64 smd: 0(-28.445,0) 0(-11.555,0) 0(-8.445,0) 0(8.445,0) 0(11.555,0) 0(28.445,0)
  rect 4.7x0.64 smd: 0(-23.175,0) 0(-16.825,0) 0(-3.175,0) 0(3.175,0) 0(16.825,0) 0(23.175,0)
  rect 0.3x1.45 smd: 1(-27.25,3.09) 2(-27.25,-3.09) 3(-26.75,3.09) 4(-26.75,-3.09) 5(-26.25,3.09) 6(-26.25,-3.09) 7(-25.75,3.09) 8(-25.75,-3.09) 9(-25.25,3.09) 10(-25.25,-3.09) 11(-24.75,3.09) 12(-24.75,-3.09) 13(-24.25,3.09) 14(-24.25,-3.09) 15(-23.75,3.09) 16(-23.75,-3.09) 17(-23.25,3.09) 18(-23.25,-3.09) 19(-22.75,3.09) 20(-22.75,-3.09) 21(-22.25,3.09) 22(-22.25,-3.09) 23(-21.75,3.09) 24(-21.75,-3.09) 25(-21.25,3.09) 26(-21.25,-3.09) 27(-20.75,3.09) 28(-20.75,-3.09) 29(-20.25,3.09) 30(-20.25,-3.09) 31(-19.75,3.09) 32(-19.75,-3.09) 33(-19.25,3.09) 34(-19.25,-3.09) 35(-18.75,3.09) 36(-18.75,-3.09) 37(-18.25,3.09) 38(-18.25,-3.09) 39(-17.75,3.09) 40(-17.75,-3.09) 41(-17.25,3.09) 42(-17.25,-3.09) 43(-16.75,3.09) 44(-16.75,-3.09) 45(-16.25,3.09) 46(-16.25,-3.09) 47(-15.75,3.09) 48(-15.75,-3.09) 49(-15.25,3.09) 50(-15.25,-3.09) 51(-14.75,3.09) 52(-14.75,-3.09) 53(-14.25,3.09) 54(-14.25,-3.09) 55(-13.75,3.09) 56(-13.75,-3.09) 57(-13.25,3.09) 58(-13.25,-3.09) 59(-12.75,3.09) 60(-12.75,-3.09) 61(-7.25,3.09) 62(-7.25,-3.09) 63(-6.75,3.09) 64(-6.75,-3.09) 65(-6.25,3.09) 66(-6.25,-3.09) 67(-5.75,3.09) 68(-5.75,-3.09) 69(-5.25,3.09) 70(-5.25,-3.09) 71(-4.75,3.09) 72(-4.75,-3.09) 73(-4.25,3.09) 74(-4.25,-3.09) 75(-3.75,3.09) 76(-3.75,-3.09) 77(-3.25,3.09) 78(-3.25,-3.09) 79(-2.75,3.09) 80(-2.75,-3.09) 81(-2.25,3.09) 82(-2.25,-3.09) 83(-1.75,3.09) 84(-1.75,-3.09) 85(-1.25,3.09) 86(-1.25,-3.09) 87(-0.75,3.09) 88(-0.75,-3.09) 89(-0.25,3.09) 90(-0.25,-3.09) 91(0.25,3.09) 92(0.25,-3.09) 93(0.75,3.09) 94(0.75,-3.09) 95(1.25,3.09) 96(1.25,-3.09) 97(1.75,3.09) 98(1.75,-3.09) 99(2.25,3.09) 100(2.25,-3.09) 101(2.75,3.09) 102(2.75,-3.09) 103(3.25,3.09) 104(3.25,-3.09) 105(3.75,3.09) 106(3.75,-3.09) 107(4.25,3.09) 108(4.25,-3.09) 109(4.75,3.09) 110(4.75,-3.09) 111(5.25,3.09) 112(5.25,-3.09) 113(5.75,3.09) 114(5.75,-3.09) 115(6.25,3.09) 116(6.25,-3.09) 117(6.75,3.09) 118(6.75,-3.09) 119(7.25,3.09) 120(7.25,-3.09) 121(12.75,3.09) 122(12.75,-3.09) 123(13.25,3.09) 124(13.25,-3.09) 125(13.75,3.09) 126(13.75,-3.09) 127(14.25,3.09) 128(14.25,-3.09) 129(14.75,3.09) 130(14.75,-3.09) 131(15.25,3.09) 132(15.25,-3.09) 133(15.75,3.09) 134(15.75,-3.09) 135(16.25,3.09) 136(16.25,-3.09) 137(16.75,3.09) 138(16.75,-3.09) 139(17.25,3.09) 140(17.25,-3.09) 141(17.75,3.09) 142(17.75,-3.09) 143(18.25,3.09) 144(18.25,-3.09) 145(18.75,3.09) 146(18.75,-3.09) 147(19.25,3.09) 148(19.25,-3.09) 149(19.75,3.09) 150(19.75,-3.09) 151(20.25,3.09) 152(20.25,-3.09) 153(20.75,3.09) 154(20.75,-3.09) 155(21.25,3.09) 156(21.25,-3.09) 157(21.75,3.09) 158(21.75,-3.09) 159(22.25,3.09) 160(22.25,-3.09) 161(22.75,3.09) 162(22.75,-3.09) 163(23.25,3.09) 164(23.25,-3.09) 165(23.75,3.09) 166(23.75,-3.09) 167(24.25,3.09) 168(24.25,-3.09) 169(24.75,3.09) 170(24.75,-3.09) 171(25.25,3.09) 172(25.25,-3.09) 173(25.75,3.09) 174(25.75,-3.09) 175(26.25,3.09) 176(26.25,-3.09) 177(26.75,3.09) 178(26.75,-3.09) 179(27.25,3.09) 180(27.25,-3.09)
  round 1.02 hole 1.02 unplated: MH(-29.24,2.03) MH(29.24,2.03)
  silkscreen extent -30.05,-3.05 30.05,3.05
RESC1005X06A#1 [mm] "Chip Resistor, 2-Leads, Body 1.00x0.50mm, OK custom footprint"
  rect 0.5x0.6 smd mask+0.051: 1(-0.5,0) 2(0.5,0)
RESC1005X06A#2 [mm] "Chip Resistor, 2-Leads, Body 1.00x0.50mm, OK custom footprint"
  rect 0.5x0.6 smd: 1(-0.5,0) 2(0.5,0)
RESC1608N [mm] "Chip Resistor, Body 1.6x0.8mm, IPC Medium Density"
  rect 0.9x1 smd: 1(-0.85,0) 2(0.85,0)
  silkscreen extent -0.77,-0.68 0.78,0.68, body extent -0.85,-0.48 0.85,0.48, height 0.6
RESC2012N [mm] "Chip Resistor, Body 2.0x1.3mm, IPC Medium Density"
  rect 1.2x1.4 smd: 1(-0.9,0) 2(0.9,0)
  silkscreen extent -0.85,-0.89 0.85,0.88, body extent -1.07,-0.7 1.07,0.7, height 0.65
S-PWSON-N6 [mm]
  rect 1.6x1 smd paste-4: 0(0,0)
  rect 0.3x0.7 smd mask+0.07: 1(-0.65,-1.15) 2(0,-1.15) 3(0.65,-1.15) 4(0.65,1.15) 5(0,1.15) 6(-0.65,1.15)
  silkscreen extent -1,-1.5 1,1, body extent -1,-1 1,1, height 0.8
Si5338 [mm]
  rrect50% 0.8x0.25 smd: 1(-1.95,1.25) 2(-1.95,0.75) 3(-1.95,0.25) 4(-1.95,-0.25) 5(-1.95,-0.75) 6(-1.95,-1.25) 13(1.95,-1.25) 14(1.95,-0.75) 15(1.95,-0.25) 16(1.95,0.25) 17(1.95,0.75) 18(1.95,1.25)
  rrect50% 0.25x0.8 smd: 7(-1.25,-1.95) 8(-0.75,-1.95) 9(-0.25,-1.95) 10(0.25,-1.95) 11(0.75,-1.95) 12(1.25,-1.95) 19(1.25,1.95) 20(0.75,1.95) 21(0.25,1.95) 22(-0.25,1.95) 23(-0.75,1.95) 24(-1.25,1.95)
  rect 2.55x2.55 smd paste-10: PAD(0,0)
  silkscreen extent -2.55,-2.17 2.17,2.55, body extent -2.07,-2.07 2.07,2.07, height 0.8
SN65DP141 [mm]
  rect 0.85x0.28 smd: 1(-2.475,2.75) 2(-2.475,2.25) 3(-2.475,1.75) 4(-2.475,1.25) 5(-2.475,0.75) 6(-2.475,0.25) 7(-2.475,-0.25) 8(-2.475,-0.75) 9(-2.475,-1.25) 10(-2.475,-1.75) 11(-2.475,-2.25) 12(-2.475,-2.75) 20(2.475,-2.75) 21(2.475,-2.25) 22(2.475,-1.75) 23(2.475,-1.25) 24(2.475,-0.75) 25(2.475,-0.25) 26(2.475,0.25) 27(2.475,0.75) 28(2.475,1.25) 29(2.475,1.75) 30(2.475,2.25) 31(2.475,2.75)
  rect 0.28x0.85 smd: 13(-1.5,-3.475) 14(-1,-3.475) 15(-0.5,-3.475) 16(0,-3.475) 17(0.5,-3.475) 18(1,-3.475) 19(1.5,-3.475) 32(1.5,3.475) 33(1,3.475) 34(0.5,3.475) 35(0,3.475) 36(-0.5,3.475) 37(-1,3.475) 38(-1.5,3.475)
  rect 2.1x4.1 smd paste-5: PAD(0,0)
  silkscreen extent -3.1,-3.6 2.6,4.1
SO-G8 [mm] "Small Outline; 8 Leads; Body Width 3.9 mm; Pitch 1.27 mm"
  rect 0.6x2.2 smd: 1(-1.905,-2.6) 2(-0.635,-2.6) 3(0.635,-2.6) 4(1.905,-2.6) 5(1.905,2.6) 6(0.635,2.6) 7(-0.635,2.6) 8(-1.905,2.6)
  silkscreen extent -2.45,-3.7 2.45,1.95
SOD-123 [mm] "SMT Diode Package from ON Semi"
  rect 0.91x1.22 smd: 1(-1.64,0) 2(1.64,0)
  silkscreen extent -1.35,-0.79 2.09,0.79
SOT23-95P240X110 [mm] "SOT-23; 3 Leads; Body 3.0 x 2.6 mm, inc. leads (LxW max)"
  rect 0.8x0.9 smd: 1(-0.95,-1) 2(0.95,-1) 3(0,1)
  silkscreen extent -1.53,-1.45 1.54,0.77
SOT363-6N [mm] "SOT363, 6-Leads, Body 2x1.3mm, Pitch 0.65mm, Lead Span 2.1mm, IPC Medium Density"
  rect 0.85x0.4 smd: 1(-0.95,0.65) 2(-0.95,0) 3(-0.95,-0.65) 4(0.95,-0.65) 5(0.95,0) 6(0.95,0.65)
  silkscreen extent -1.37,-1.09 0.64,1.09, body extent -0.63,-1 0.63,1, height 1
TP-PTH-25/45 [mil] "Test point, plated through-hole, 25/45mil"
  round 45 hole 25: 1(0,0)
TP-SMD40 [mm] "Test point, surface-mount, 40mil"
  round 1 smd paste-2: 1(0,0)
TPD8S009DSMR [mm]
  rect 0.3x1.45 smd: 1(-2.75,-0.925) 2(-2.25,-0.925) 3(-1.75,-0.925) 4(-1.25,-0.925) 5(-0.75,-0.925) 6(-0.25,-0.925) 7(0.25,-0.925) 8(0.75,-0.925) 9(1.25,-0.925) 10(1.75,-0.925) 11(2.25,-0.925) 12(2.75,-0.925) 13(1.5,0.925) 14(0,0.925) 15(-1.5,0.925)
  silkscreen extent -3.3,-1.85 3.3,1.3
TPS7A90 [mm]
  rect 0.6x0.25 smd: 1(-1.15,1) 2(-1.15,0.5) 3(-1.15,0) 4(-1.15,-0.5) 5(-1.15,-1) 6(1.15,-1) 7(1.15,-0.5) 8(1.15,0) 9(1.15,0.5) 10(1.15,1)
  rect 1.2x2 smd paste-10: PAD(0,0)
  silkscreen extent -1.65,-1.35 1.25,1.35
TXB0108DQSR [mm] "TI R-PUSON-N20"
  rect 0.2x1 smd mask+0.051: 1(-1.8,-0.9) 2(-1.4,-0.9) 3(-1,-0.9) 4(-0.6,-0.9) 5(-0.2,-0.9) 6(0.2,-0.9) 7(0.6,-0.9) 8(1,-0.9) 9(1.4,-0.9) 10(1.8,-0.9) 11(1.8,0.9) 12(1.4,0.9) 13(1,0.9) 14(0.6,0.9) 15(0.2,0.9) 16(-0.2,0.9) 17(-0.6,0.9) 18(-1,0.9) 19(-1.4,0.9) 20(-1.8,0.9)
  silkscreen extent -2.16,-1.6 2.16,1.01, body extent -2,-1 2,1, height 0.5
WQFN-30 [mm]
  rect 0.1x0.1 smd: 1(-1.2,1.8) 10(-1.2,-1.8) 11(-0.8,-2.2) 15(0.8,-2.2) 16(1.2,-1.8) 25(1.2,1.8) 26(0.8,2.2) 30(-0.8,2.2)
  rect 0.5x0.2 smd: 2(-1.2,1.4) 3(-1.2,1) 4(-1.2,0.6) 5(-1.2,0.2) 6(-1.2,-0.2) 7(-1.2,-0.6) 8(-1.2,-1) 9(-1.2,-1.4) 17(1.2,-1.4) 18(1.2,-1) 19(1.2,-0.6) 20(1.2,-0.2) 21(1.2,0.2) 22(1.2,0.6) 23(1.2,1) 24(1.2,1.4)
  rect 0.2x0.5 smd: 12(-0.4,-2.2) 13(0,-2.2) 14(0.4,-2.2) 27(0.4,2.2) 28(0,2.2) 29(-0.4,2.2)
  rect 1.2x3.2 smd: PAD(0.015,0.02)
  L1-TOP region: -1.45,1.9 -1.45,1.7 -0.95,1.7 -0.95,1.81 -1.04,1.9
  L1-TOP region: -0.9,2.45 -0.7,2.45 -0.7,1.95 -0.81,1.95 -0.9,2.04
  L1-TOP region: -0.9,-2.45 -0.7,-2.45 -0.7,-1.95 -0.81,-1.95 -0.9,-2.04
  L1-TOP region: 1.45,-1.9 1.45,-1.7 0.95,-1.7 0.95,-1.81 1.04,-1.9
  L1-TOP region: 0.9,2.45 0.7,2.45 0.7,1.95 0.81,1.95 0.9,2.04
  L1-TOP region: -1.45,-1.9 -1.45,-1.7 -0.95,-1.7 -0.95,-1.81 -1.04,-1.9
  L1-TOP region: 0.9,-2.45 0.7,-2.45 0.7,-1.95 0.81,-1.95 0.9,-2.04
  L1-TOP region: 1.45,1.9 1.45,1.7 0.95,1.7 0.95,1.81 1.04,1.9
  silkscreen extent -1.65,-2.32 1.3,2.32
XAL60XX [mm]
  rect 1.43x5.5 smd: 1(-2.02,0) 2(2.02,0)
  silkscreen extent -3.25,-3.35 3.25,3.35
